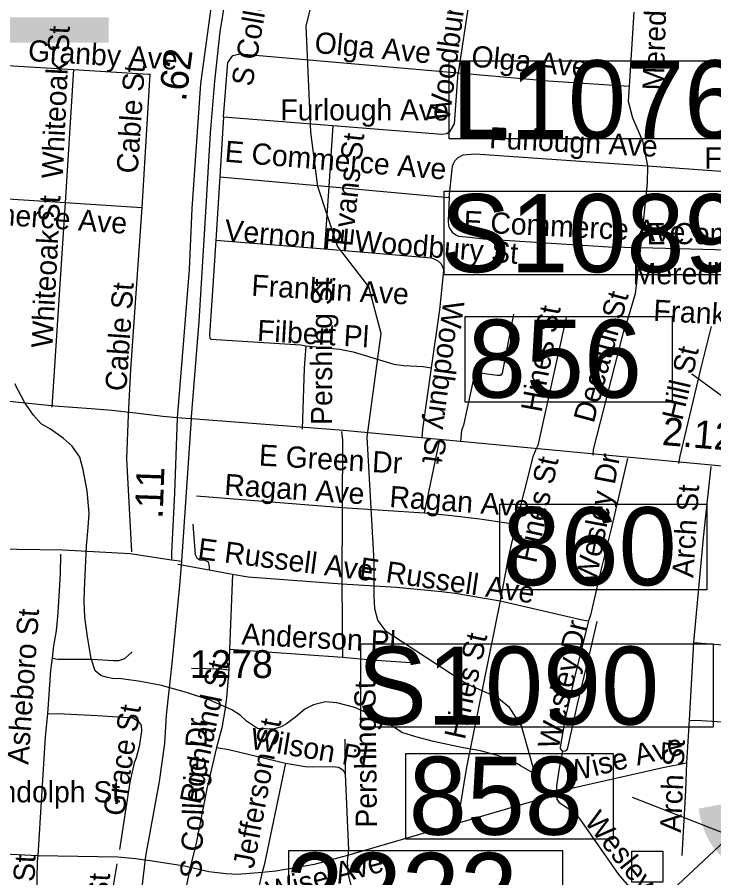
# Model space of a CAD drawing. Extents: x 1662474 to 1856135, y 779280 to 917889.
# Drawn here: x 1705631 to 1708754, y 801486 to 805345 of the extents above; entities that cross this region are included whole.
import ezdxf

# ---------------------------------------------------------------- set-up
doc = ezdxf.new("R2010")
doc.units = 0
for name, color, linetype in [('Exist Hydrographic Misc Water Feature', 7, 'Continuous'), ('Exist Road Non-System Structure Non-Sys Other Attributed CELL', 7, 'Continuous'), ('Exist Road Non-System Structure Non-Sys Other Number Label', 7, 'Continuous'), ('Exist Road Non-System Type 51', 7, 'Continuous'), ('Exist Road Non-System Type 51 Label', 7, 'Continuous'), ('Exist Road Primary Interstate Structure Cantilever Sign Number Label', 7, 'Continuous'), ('Exist Road Primary US Structure Ovrhead Sign CELL', 7, 'Continuous'), ('Exist Road Primary US Structure Standard Bridge Number Label', 7, 'Continuous'), ('Exist Road Secondary Mileage Tenths English Label', 7, 'Continuous'), ('Exist Road Secondary Type 51 Attributed', 7, 'Continuous'), ('Exist Road Secondary Type 51 Divided Attributed', 7, 'Continuous'), ('Exist Road Secondary Type 51 Label', 7, 'Continuous'), ('Exist Road Secondary Type 51 Number Label', 7, 'Continuous'), ('Exist Road Secondary Type 51 Undivided 4 Lane Attributed', 7, 'Continuous'), ('Exist Utilities Electrical Transmission Line', 7, 'Continuous')]:
    doc.layers.add(name, color=color, linetype=linetype)

msp = doc.modelspace()

# ---------------------------------------------------------------- linework, layer by layer
at = {"layer": 'Exist Hydrographic Misc Water Feature'}
for points in [[(1707956.9, 801938.8), (1707892.7, 802168.3), (1707838.7, 802249.2), (1707781.3, 802296.5), (1707646.3, 802354.5), (1707285, 802590.7), (1707247.9, 802641.3), (1707234.4, 802692), (1707231, 802752.7), (1707231, 802904.5), (1707200.6, 803461.3), (1707263, 803927.3), (1707207.1, 804135.2), (1707067.1, 804318.6), (1706978.1, 804586.3), (1706947, 804829.8), (1706926.1, 805306.2), (1706996.1, 805587.1), (1706989.1, 805728.3), (1706964.1, 805771.5)], [(1707961.2, 801946.2), (1707891.1, 801986.6), (1707859, 802006.3), (1707784.3, 802034.6), (1707708.5, 802055.3), (1707622.6, 802070.4), (1707497.8, 802098), (1707417.9, 802118.7), (1707356, 802137.8), (1707282.6, 802186.6), (1707145, 802249.9), (1707063.3, 802270.6), (1707013.3, 802275.1), (1706959.1, 802261.6), (1706920.9, 802242), (1706880.7, 802208.3), (1706838.3, 802176.8), (1706814.2, 802163), (1706780, 802153.2), (1706708.1, 802156), (1706658.4, 802188.5), (1706630.7, 802214.7), (1706592.8, 802239.1), (1706495.2, 802282), (1706389.5, 802317), (1706277.8, 802348), (1706183.9, 802367), (1706098, 802377.8), (1706058, 802380.2), (1706030.1, 802386.4), (1706006.2, 802392.7), (1705980.3, 802414.9), (1705962.8, 802469.1), (1705945.8, 802567.3), (1705934.5, 802655.5), (1705931.3, 802727.5), (1705931.8, 802777.5), (1705941.6, 802973.4), (1705948.4, 803057.5), (1705953, 803121.4), (1705943.9, 803221.5), (1705926.8, 803315.7), (1705911.4, 803371.9), (1705877.8, 803422.2), (1705836.2, 803456.7), (1705780.4, 803497.2), (1705738.7, 803521.6), (1705703.1, 803559.9), (1705665.6, 803616.3), (1705620.5, 803700.7)]]:
    msp.add_lwpolyline(points, dxfattribs=at)
at = {"layer": 'Exist Road Non-System Structure Non-Sys Other Attributed CELL'}
msp.add_lwpolyline([(1708386.1, 801605.5), (1708525.1, 801605.5), (1708525.1, 801466.4), (1708386.1, 801466.4)], close=True, dxfattribs=at)
at = {"layer": 'Exist Road Non-System Type 51'}
for p, q in [((1707657.6, 805421.7), (1707607.4, 805094.9)), ((1708396.1, 805367.9), (1708374.4, 805035)), ((1705563.4, 805129.8), (1705883.1, 805110.6)), ((1705883.1, 805110.6), (1705845.5, 804513.8)), ((1706556, 804898.5), (1706539.2, 804629.2)), ((1706556, 804898.5), (1707045.5, 804859.4)), ((1707045.5, 804859.4), (1707027.4, 804585.2)), ((1706539.2, 804629.2), (1706520.9, 804345.5)), ((1706539.2, 804629.2), (1707027.4, 804585.2)), ((1707027.4, 804585.2), (1707009, 804305.7)), ((1707027.4, 804585.2), (1707567.9, 804536.1)), ((1705525.6, 804534.5), (1705845.5, 804513.8)), ((1705845.5, 804513.8), (1705785.9, 803596.5)), ((1705845.5, 804513.8), (1706189.1, 804491.8)), ((1706520.9, 804345.5), (1706505.1, 804095.9)), ((1706520.9, 804345.5), (1707009, 804305.7)), ((1707524.5, 804033.2), (1707486.4, 803772.6)), ((1707524.5, 803451.4), (1707454.9, 803122.2)), ((1706434.5, 803198.1), (1707087.2, 803146.1)), ((1707087.2, 803146.1), (1707086.6, 802804.6)), ((1707087.2, 803146.1), (1707454.9, 803122.2)), ((1706351.2, 802892.6), (1706491.6, 802867.1)), ((1706491.6, 802867.1), (1706595.4, 802847.4)), ((1706595.4, 802847.4), (1706582.8, 802510.9)), ((1707086.6, 802804.6), (1707088.9, 802475.2)), ((1706582.8, 802510.9), (1706579.4, 802418.5)), ((1706582.8, 802510.9), (1707088.9, 802475.2)), ((1708662.5, 802541.1), (1708643.6, 802192.9)), ((1708643.6, 802192.9), (1708631.9, 802002)), ((1707099.4, 802108.1), (1707100.6, 801951.4)), ((1707114, 801587.9), (1707615.1, 801733.8)), ((1705395.9, 801601.8), (1705723.2, 801585.8)), ((1706161, 801572.1), (1706216.6, 801565))]:
    msp.add_line(p, q, dxfattribs=at)
for points in [[(1706556, 804898.5), (1706574.9, 805141.9), (1706597.5, 805172.9), (1706630.6, 805180.9), (1707607.4, 805094.9)], [(1705883.1, 805110.6), (1706218.8, 805089.4), (1706226.1, 805088.9), (1706189.1, 804491.8)], [(1707045.5, 804859.4), (1707534.1, 804820.4), (1707557, 804824), (1707572.8, 804834), (1707591.6, 804867.4), (1707607.4, 805094.9)], [(1707607.4, 805094.9), (1708011.9, 805059.4), (1708374.4, 805035)], [(1708374.4, 805035), (1708369.9, 804967.9), (1708390.1, 804893.6), (1708435, 804790.7), (1708456.8, 804677.9)], [(1707567.9, 804536.1), (1707583.2, 804676.2), (1707587, 804689.4), (1707593.5, 804701.4), (1707607.4, 804716.4), (1707630.5, 804727.7), (1707683.6, 804732.4), (1708456.8, 804677.9)], [(1708456.8, 804677.9), (1708455.1, 804600.4), (1708425.5, 804311.7)], [(1708456.8, 804677.9), (1708827.4, 804652.1), (1708984.9, 804651.9)], [(1707567.9, 804536.1), (1707562.6, 804431.9), (1707564.1, 804411.2), (1707568.9, 804398.2), (1707580.4, 804381.2), (1707596.9, 804368.9), (1707610.1, 804363.7), (1707660.8, 804357.9), (1707720.9, 804351.1), (1708281.6, 804315.1), (1708425.5, 804311.7)], [(1706189.1, 804491.8), (1706139.2, 803765.5), (1706128.4, 803562.1)], [(1707009, 804305.7), (1707488.9, 804266.5), (1707515.9, 804254.4), (1707530.5, 804239.8), (1707540, 804221.2), (1707542.9, 804207.2), (1707524.5, 804033.2)], [(1708425.5, 804311.7), (1708401.4, 804105.1), (1708365.1, 803983.1)], [(1708425.5, 804311.7), (1708984.4, 804297.8), (1709146.8, 804288.4)], [(1706505.1, 804095.9), (1706493, 803920.1), (1706495.1, 803906.4), (1706499.4, 803900.9), (1706903, 803875.2), (1706924.2, 803871)], [(1707856.8, 804013.2), (1707804.9, 803748.4), (1707797.4, 803738.8), (1707783.6, 803737.7), (1707694.9, 803750.5), (1707684.4, 803741.9), (1707676.8, 803722.8), (1707632.1, 803516.2), (1707622.4, 803492), (1707619, 803441.1)], [(1708092.1, 803998.4), (1707965.1, 803425.1), (1707955.8, 803407)], [(1708365.1, 803983.1), (1708358.1, 803972.4), (1708214, 803406.2), (1708211.4, 803381.5)], [(1708743.1, 803957.6), (1708696.1, 803773.4), (1708601.4, 803377.1), (1708596.6, 803343.4)], [(1706924.2, 803871), (1706917.9, 803771.8), (1706909.2, 803497.8)], [(1706924.2, 803871), (1707077, 803857.1), (1707136.9, 803844.5), (1707320, 803789.9), (1707362.9, 803783.9), (1707451.2, 803778.6), (1707486.4, 803772.6)], [(1707486.4, 803772.6), (1707448.1, 803497.5), (1707445, 803458.7)], [(1706128.4, 803562.1), (1706120.6, 803364.4), (1706143.6, 802948.2)], [(1707085.1, 803487), (1707088.9, 803448.2), (1707087.2, 803146.1)], [(1707955.8, 803407), (1707942.6, 803373.7), (1707865.9, 803071.5)], [(1708367.8, 803366), (1708294.6, 803051.6), (1708252, 802883.4), (1708200.9, 802663.9), (1708191.9, 802639)], [(1708741, 803329.9), (1708706.9, 803009.9), (1708662.5, 802541.1)], [(1707454.9, 803122.2), (1707564.6, 803112.2), (1707705.1, 803095.7), (1707865.9, 803071.5)], [(1706419, 803072.4), (1706428.8, 802936.1), (1706435.9, 802920.4), (1706450.2, 802912), (1706472, 802910.7), (1706486.4, 802903.6), (1706491.4, 802881.5), (1706491.6, 802867.1)], [(1707865.9, 803071.5), (1707832.4, 802920.7), (1707795.9, 802727.4)], [(1705824.8, 802937.7), (1705823.5, 802851.1), (1705812.8, 802675), (1705805.9, 802592.9), (1705793.9, 802525.6), (1705787, 802470.5)], [(1706595.4, 802847.4), (1706666, 802835.9), (1707086.6, 802804.6)], [(1707086.6, 802804.6), (1707331.9, 802789.9), (1707533.4, 802770.5), (1707594.9, 802762.6), (1707795.9, 802727.4)], [(1707795.9, 802727.4), (1707645, 801982.6), (1707609, 801764.5), (1707615.1, 801733.8)], [(1707795.9, 802727.4), (1708170.9, 802641.1), (1708191.9, 802639)], [(1708191.9, 802639), (1708127.9, 802378.9), (1708088.5, 802199.9), (1708065.1, 802072.6), (1708065.4, 802066.1), (1708069.4, 802060), (1708076.1, 802053.2)], [(1708229.5, 802636.1), (1708201.9, 802512.5), (1708141.6, 802264.5), (1708098.2, 802069.2), (1708094.6, 802057.9), (1708087.5, 802053.4), (1708076.1, 802053.2)], [(1708662.5, 802541.1), (1708852, 802526.4), (1709098.5, 802517.5)], [(1705787, 802470.5), (1705812.4, 802465.8), (1705967.6, 802466.4), (1706063.1, 802459.8), (1706087, 802460.9), (1706112.8, 802469.8), (1706145.5, 802499.1)], [(1707088.9, 802475.2), (1707220, 802463.4), (1707437.4, 802449.2)], [(1705787, 802470.5), (1705780.4, 802417.8), (1705766.8, 802221.2)], [(1706411.6, 802426.7), (1706544.5, 802423), (1706579.4, 802418.5)], [(1706579.4, 802418.5), (1706569.6, 802295.2), (1706562.9, 802245.1), (1706548.4, 802158.2), (1706524.5, 802069.8)], [(1705766.8, 802221.2), (1705756, 802118.9), (1705723.2, 801585.8)], [(1705766.8, 802221.2), (1705811.4, 802222.5), (1705990.4, 802214.6), (1706149.8, 802203.9), (1706173.6, 802188.9), (1706185.9, 802171), (1706188.6, 802143.2), (1706177.9, 802074.4), (1706164.4, 802024.6), (1706155, 802001.8), (1706136.1, 801915.7), (1706088.9, 801613.9)], [(1708643.6, 802192.9), (1708699, 802192), (1709117.9, 802165.2)], [(1706524.5, 802069.8), (1706480.4, 801884.9), (1706431.9, 801634), (1706406.9, 801534.6)], [(1706524.5, 802069.8), (1706579.1, 802061.4), (1706833.6, 802000.9)], [(1708076.1, 802053.2), (1708061.8, 801986.5), (1708049.4, 801898.9), (1708048.9, 801866.6)], [(1706833.6, 802000.9), (1706738.4, 801542.7), (1706729.2, 801511.2)], [(1706833.6, 802000.9), (1706921.6, 801984.9), (1706958.1, 801983.4), (1707042.4, 801985.2), (1707073.4, 801982.1), (1707091.9, 801968.9), (1707100.6, 801951.4)], [(1708048.9, 801866.6), (1708083.2, 801880.2), (1708525, 801980.5), (1708631.9, 802002)], [(1708631.9, 802002), (1708627.9, 801877.4), (1708611.1, 801585.8)], [(1707100.6, 801951.4), (1707116.6, 801610.7), (1707114, 801587.9)], [(1707615.1, 801733.8), (1707938.1, 801828.2), (1708007.4, 801849.5), (1708048.9, 801866.6)], [(1708048.9, 801866.6), (1708051, 801838.5), (1708059.4, 801825.9), (1708119, 801785.2), (1708141.6, 801764.2), (1708158.6, 801743.8), (1708327.1, 801501.2), (1708382.2, 801436.4), (1708468.9, 801355.9), (1708566.5, 801283.1), (1708641.5, 801239.9), (1708711.4, 801207.2), (1708780.1, 801181.2), (1708930.8, 801130.4), (1709096.6, 801064.8), (1709154.1, 801047.7), (1709211.1, 801035.6), (1709308.1, 801025.9), (1709398.8, 801021.8)], [(1705723.2, 801585.8), (1705719.9, 801559.8), (1705716.9, 801406.8), (1705692.8, 800708.1)], [(1705723.2, 801585.8), (1706081.5, 801580.2), (1706161, 801572.1)], [(1706729.2, 801511.2), (1706789.9, 801516.8), (1706963.4, 801547.7), (1707114, 801587.9)], [(1707114, 801587.9), (1707110.6, 801556.1), (1707114.5, 801500.4), (1707159.6, 801319.4), (1707166, 801253.8)], [(1706077.2, 801548.8), (1706052.4, 801395.8), (1706039.8, 801289.4), (1706034.5, 801214.6), (1706027.9, 800854.2), (1706021.9, 800693.7)], [(1706216.6, 801565), (1706382.2, 801540.6), (1706406.9, 801534.6)], [(1706406.9, 801534.6), (1706384.9, 801431.2), (1706376.5, 801367.4), (1706360.5, 800865.6)], [(1706406.9, 801534.6), (1706489.4, 801515.2), (1706568.4, 801505.4), (1706618.8, 801502.6), (1706729.2, 801511.2)], [(1706729.2, 801511.2), (1706708.5, 801419.4), (1706702.5, 801366.6), (1706697.5, 801073.7), (1706693, 801038.8)]]:
    msp.add_lwpolyline(points, dxfattribs=at)
at = {"layer": 'Exist Road Primary Interstate Structure Cantilever Sign Number Label'}
msp.add_lwpolyline([(1707567.4, 805148.6), (1709130.3, 805148.6), (1709130.3, 804799.6), (1707567.4, 804799.6)], close=True, dxfattribs=at)
at = {"layer": 'Exist Road Primary US Structure Ovrhead Sign CELL'}
for points in [[(1707545.7, 804564.1), (1709125.7, 804564.1), (1709125.7, 804190), (1707545.7, 804190)], [(1707172, 802535.6), (1708752, 802535.6), (1708752, 802161.4), (1707172, 802161.4)]]:
    msp.add_lwpolyline(points, close=True, dxfattribs=at)
at = {"layer": 'Exist Road Primary US Structure Standard Bridge Number Label'}
for p, q in [((1710930.6, 802076.4), (1708656.2, 803744.8)), ((1712142.7, 800374.6), (1708390.3, 801846.8))]:
    msp.add_line(p, q, dxfattribs=at)
for points in [[(1707638.7, 804003.2), (1708567.7, 804003.2), (1708567.7, 803619.1), (1707638.7, 803619.1)], [(1707794.2, 803162.2), (1708723.2, 803162.2), (1708723.2, 802778.1), (1707794.2, 802778.1)], [(1707373.8, 802043.6), (1708302.8, 802043.6), (1708302.8, 801659.5), (1707373.8, 801659.5)], [(1706848.9, 801609.4), (1708076.5, 801609.4), (1708076.5, 801231.3), (1706848.9, 801231.3)]]:
    msp.add_lwpolyline(points, close=True, dxfattribs=at)
at = {"layer": 'Exist Road Secondary Type 51 Attributed'}
for points in [[(1706348.1, 803547.9), (1706283.6, 803554.9), (1706161.4, 803569), (1706055.8, 803580.7), (1705962.1, 803589.1), (1705797.9, 803600.4), (1705491.9, 803632.2), (1705181.9, 803668), (1704848.8, 803702.3), (1704701.4, 803705), (1704431.3, 803720.3), (1704053.8, 803729.7), (1703881.9, 803737.7), (1703694.7, 803740.1), (1703601.7, 803736.3)], [(1706412.3, 803544.3), (1706408.7, 803544.6), (1706348.1, 803547.9)], [(1703631.4, 803052.5), (1705631, 802960), (1705835.8, 802956.1), (1706136.8, 802939.6), (1706321.9, 802912.3)], [(1706119.7, 799964.7), (1706129.2, 800449), (1706161.5, 801117.7), (1706190.6, 801444), (1706207.7, 801583), (1706268.7, 801917.7), (1706292.3, 802088.1), (1706300.8, 802216), (1706325, 802447.3), (1706360, 802796.8), (1706368.3, 802905.4)], [(1706321.9, 802912.3), (1706368.3, 802905.4)]]:
    msp.add_lwpolyline(points, dxfattribs=at)
at = {"layer": 'Exist Road Secondary Type 51 Divided Attributed'}
for points in [[(1706412.3, 803544.3), (1706412.9, 803552.5), (1706447.2, 803980.4), (1706472.2, 804396.4), (1706497.2, 804824.8), (1706516.6, 805057.9), (1706540.5, 805279.8), (1706565.2, 805426.9), (1706582.4, 805517.8), (1706622.7, 805738.6), (1706654.3, 805968.2), (1706682.3, 806159.3), (1706698.1, 806294.2), (1706715.7, 806408.2), (1706742, 806550.1), (1706776.7, 806716.3)], [(1706721, 806706.8), (1706675.3, 806527.3), (1706636.7, 806346.8), (1706589.4, 805970), (1706522.8, 805537.1), (1706505.3, 805432), (1706452.6, 805046.3), (1706414, 804487.2), (1706401.8, 804213.8), (1706376.2, 803896.1), (1706348.1, 803547.9)], [(1706348.1, 803547.9), (1706336.1, 803210.6), (1706321.9, 802943.6), (1706321.9, 802912.3)], [(1706368.3, 802905.4), (1706412.3, 803544.3)]]:
    msp.add_lwpolyline(points, dxfattribs=at)
at = {"layer": 'Exist Road Secondary Type 51 Undivided 4 Lane Attributed'}
msp.add_lwpolyline([(1710985.6, 803675.5), (1710725.9, 803556.2), (1710698, 803547.5), (1710519.2, 803462.1), (1710452.1, 803424), (1710369.6, 803383.1), (1710325.6, 803359.1), (1710289.6, 803341.2), (1710233.6, 803313.2), (1710183.6, 803295.2), (1710171.6, 803287.2), (1710138.7, 803279.3), (1710113.7, 803269.2), (1710086.1, 803264.2), (1709931.9, 803248.2), (1709742.2, 803246.6), (1709331.9, 803280.9), (1707093.6, 803491.7), (1706412.3, 803544.3)], dxfattribs=at)
at = {"layer": 'Exist Utilities Electrical Transmission Line'}
msp.add_lwpolyline([(1708361.1, 801237.7), (1708802.7, 801651.1), (1709070.2, 801905.3), (1709757.3, 802555.4), (1710602.2, 803351), (1710839.1, 803555.2), (1711183.6, 803888.6), (1711682.4, 804367.2), (1712000.4, 804670.6), (1712495, 805135.2), (1713050.2, 805659.3), (1713449.3, 806029.3), (1713779.5, 806348.5), (1714124.4, 806683.5), (1714460.6, 806996.7), (1714551.9, 807077.2), (1714763.8, 807525.9), (1714928.9, 807877.4), (1715065, 808165.4), (1715330.2, 808405.6), (1715755.5, 808789.2), (1716106.2, 809133.9), (1716438.8, 809461.3)], dxfattribs=at)

# ---------------------------------------------------------------- texts
at = {"layer": 'Exist Road Non-System Structure Non-Sys Other Number Label'}
for s, p in [('J392', (1703067.2, 805230.2)), ('J422', (1708663.9, 801535.9))]:
    msp.add_text(s, height=1049.86, dxfattribs=at).set_placement(p)
at = {"layer": 'Exist Road Non-System Type 51 Label'}
for s, rotation, p in [('Meredith St', 88.1827, (1708529, 805015.2)), ('Woodbury St', 82.5327, (1707568.2, 804874.2)), ('Whiteoak St', 87.2994, (1705834.7, 804619.3)), ('Olga Ave', 354.7854, (1706961.2, 805185)), ('Granby Ave', 356.5814, (1705677.5, 805148.7)), ('Olga Ave', 354.567, (1707664, 805124.1)), ('Cable St', 86.0708, (1706170.5, 804641.8)), ('Furlough Ave', 357.0721, (1707745.6, 804757.3)), ('E Commerce Ave', 355.344, (1706558.8, 804697.1)), ('Evans St', 83.888, (1707133.2, 804313.9)), ('E Commerce Ave', 355.912, (1705127.4, 804444.4)), ('Whiteoak St', 86.9458, (1705788.6, 803859.8)), ('E Commerce Ave', 357.1516, (1707630.7, 804382.5)), ('Vernon Pl', 355.083, (1706557.6, 804343.7)), ('Woodbury St', 355.5147, (1707141.1, 804295.8)), ('Franklin Ave', 356.7131, (1706679.2, 804096.5)), ('Pershing St', 90, (1707042.9, 803516.7)), ('Cable St', 85.9995, (1706119.6, 803665.7)), ('Decatur St', 74.7603, (1708215.2, 803521.2)), ('Woodbury St', 262.5084, (1707542.1, 804077.7)), ('Franklin Ave', 356.7192, (1708481.1, 803984.1)), ('Hines St', 79.606, (1707981.7, 803569.5)), ('Filbert Pl', 356.6567, (1706704.9, 803893.4)), ('Hill St', 76.9727, (1708613, 803532.7)), ('Hines St', 77.7738, (1707957.1, 802893.2)), ('Wesley Dr', 79.2386, (1708225.4, 802802.3)), ('Ragan Ave', 356.1432, (1706557.4, 803203)), ('Arch St', 86.3113, (1708662.1, 802830)), ('Ragan Ave', 355.9071, (1707297.7, 803149.1)), ('E Russell Ave', 352.7208, (1706436.8, 802915.9)), ('E Russell Ave', 351.7227, (1707160.9, 802829.9)), ('Asheboro St', 86.0428, (1705680.8, 801991.7)), ('Wesley Dr', 76.8982, (1708056.4, 802057.2)), ('Anderson Pl', 357.0296, (1706634.8, 802532.6)), ('Hines St', 77.7738, (1707637.7, 802102.5)), ('Richland St', 78.4464, (1706451.5, 801811.9)), ('Pershing St', 90.6292, (1707244.1, 801711.8)), ('Grace St', 81.1975, (1706109.4, 801758.7)), ('Jefferson St', 79.3468, (1706690.7, 801523.6)), ('Wilson Pl', 350.5323, (1706671.5, 802065.4)), ('Wise Ave', 13.9593, (1708102.9, 801912.4)), ('Arch St', 87.6322, (1708607.4, 801687.5)), ('Wesley Dr', 308.3841, (1708169.8, 801738.2)), ('Asheboro St', 87.2544, (1705680.2, 800888.2)), ('Wise Ave', 15.2635, (1706763.9, 801375.3)), ('Grace St', 86.7431, (1706019, 801004.1))]:
    msp.add_text(s, height=95, rotation=rotation, dxfattribs=at).set_placement(p)
for s, p in [('Furlough Ave', (1706810.8, 804881.8)), ('Furlough Ave', (1708711.8, 804665.9)), ('E Commerce Ave', (1708453.2, 804326.9)), ('Meredith St', (1708391.1, 804147.4)), ('Randolph St', (1705393.4, 801824.5))]:
    msp.add_text(s, height=95, dxfattribs=at).set_placement(p)
at = {"layer": 'Exist Road Primary Interstate Structure Cantilever Sign Number Label'}
msp.add_text('L1076', height=350, dxfattribs=at).set_placement((1707579.9, 804801.7))
at = {"layer": 'Exist Road Primary US Structure Ovrhead Sign CELL'}
for s, p in [('S1089', (1707529.6, 804201.6)), ('S1090', (1707155.9, 802173))]:
    msp.add_text(s, height=350, dxfattribs=at).set_placement(p)
at = {"layer": 'Exist Road Primary US Structure Standard Bridge Number Label'}
for s, p in [('856', (1707651.3, 803638.9)), ('860', (1707806.8, 802797.9)), ('858', (1707386.4, 801679.2)), ('2222', (1706834.3, 801247.8))]:
    msp.add_text(s, height=350, dxfattribs=at).set_placement(p)
at = {"layer": 'Exist Road Secondary Mileage Tenths English Label'}
for s, rotation, p in [('.62', 82.2714, (1706386.6, 804964.3)), ('2.12', 355.2314, (1708519.6, 803427.1)), ('.11', 87.9639, (1706282.7, 803094.7))]:
    msp.add_text(s, height=125, rotation=rotation, dxfattribs=at).set_placement(p)
at = {"layer": 'Exist Road Secondary Type 51 Label'}
for s, rotation, p in [('S College Dr', 80.1257, (1706684.5, 805030.8)), ('E Green Dr', 356.6962, (1706712.8, 803334.8)), ('S College Dr', 87.755, (1706456.5, 801483))]:
    msp.add_text(s, height=95, rotation=rotation, dxfattribs=at).set_placement(p)
at = {"layer": 'Exist Road Secondary Type 51 Number Label'}
msp.add_text('1278', height=125, dxfattribs=at).set_placement((1706405.1, 802381.8))

doc.saveas('drawing.dxf')
